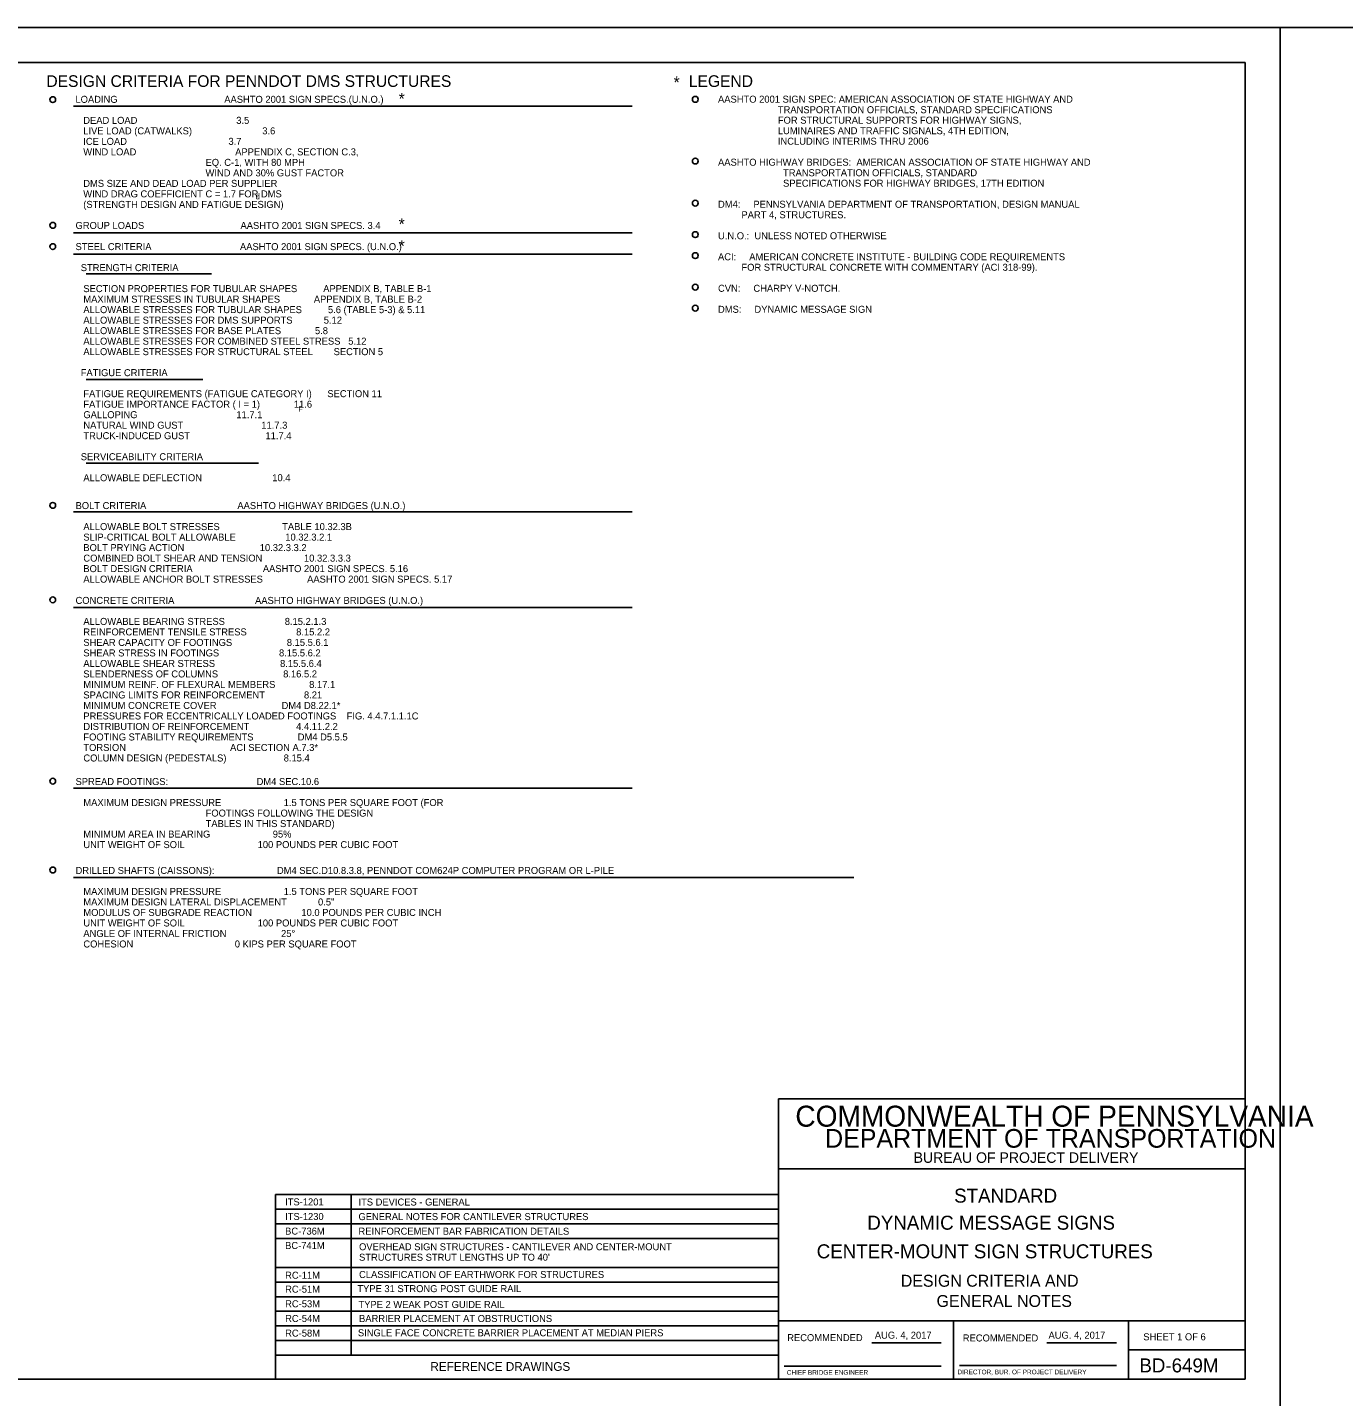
# Model space of a CAD drawing. Extents: x 3829340 to 3831660, y 499389 to 501171.
# Drawn here: x 3829644 to 3830208, y 500585 to 501171 of the extents above; entities that cross this region are included whole.
import ezdxf

# ---------------------------------------------------------------- set-up
doc = ezdxf.new("R2010")
doc.units = 0
for name, color, linetype in [('10', 7, 'Continuous'), ('13', 7, 'Continuous'), ('2', 7, 'Continuous'), ('DIM TXT', 7, 'Continuous'), ('PLT-BNDY', 7, 'Continuous')]:
    doc.layers.add(name, color=color, linetype=linetype)

msp = doc.modelspace()

# ---------------------------------------------------------------- linework, layer by layer
at = {"layer": '10'}
for p, q in [((3829664.03, 501137.44), (3829903.36, 501137.44)), ((3829664.03, 501083.16), (3829903.36, 501083.16)), ((3829664.03, 501073.99), (3829903.36, 501073.99)), ((3829669.36, 501065.68), (3829723.15, 501065.68)), ((3829669.36, 501020.29), (3829719.35, 501020.29)), ((3829669.36, 500984.49), (3829743.23, 500984.49)), ((3829664.03, 500963.68), (3829903.36, 500963.68)), ((3829664.03, 500922.74), (3829903.36, 500922.74)), ((3829664.03, 500845.32), (3829903.36, 500845.32)), ((3829664.03, 500807.06), (3829998.27, 500807.06))]:
    msp.add_line(p, q, dxfattribs=at)
at = {"layer": '13'}
for p, q in [((3829750.49, 500671.23), (3829965.96, 500671.23)), ((3829750.5, 500592.19), (3829750.5, 500671.23)), ((3829782.96, 500602.47), (3829782.96, 500671.23)), ((3829750.49, 500664.98), (3829965.96, 500664.98)), ((3829750.49, 500658.73), (3829965.96, 500658.73)), ((3829750.49, 500652.48), (3829965.96, 500652.48)), ((3829750.49, 500639.98), (3829965.96, 500639.98)), ((3829750.49, 500633.73), (3829965.96, 500633.73)), ((3829750.49, 500627.48), (3829965.96, 500627.48)), ((3829750.49, 500621.23), (3829965.96, 500621.23)), ((3829750.49, 500614.98), (3829965.96, 500614.98)), ((3829750.49, 500608.72), (3829965.96, 500608.72)), ((3829750.49, 500602.47), (3829965.96, 500602.47))]:
    msp.add_line(p, q, dxfattribs=at)
at = {"layer": '2'}
for p, q in [((3829379.96, 501156.19), (3830165.96, 501156.19)), ((3830165.96, 501156.19), (3830165.96, 500592.19)), ((3830165.96, 500712.19), (3829965.96, 500712.19)), ((3829965.96, 500712.19), (3829965.96, 500592.19)), ((3830165.96, 500682.19), (3829965.96, 500682.19)), ((3830165.96, 500617.19), (3829965.96, 500617.19)), ((3830040.96, 500592.19), (3830040.96, 500617.19)), ((3830115.96, 500617.19), (3830115.96, 500592.19)), ((3830005.93, 500607.69), (3830035.69, 500607.69)), ((3830080.93, 500607.69), (3830110.83, 500607.69)), ((3830115.96, 500604.69), (3830165.96, 500604.69)), ((3829968.46, 500597.69), (3830035.69, 500597.69)), ((3830043.59, 500598.06), (3830110.83, 500598.06)), ((3830165.96, 500592.19), (3829379.96, 500592.19)), ((3829965.96, 500592.19), (3829968.53, 500592.19))]:
    msp.add_line(p, q, dxfattribs=at)
at = {"layer": 'DIM TXT'}
for centre in [(3829655.1, 501140.24), (3829655.1, 501140.24), (3829930.36, 501140.37), (3829930.36, 501113.92), (3829930.36, 501095.92), (3829655.1, 501086.4), (3829930.36, 501082.42), (3829655.1, 501077.29), (3829930.36, 501073.43), (3829930.36, 501059.93), (3829930.36, 501050.93), (3829655.1, 500966.44), (3829655.1, 500925.96), (3829655.1, 500848.32), (3829655.1, 500810.26)]:
    msp.add_circle(centre, 1.25, dxfattribs=at)
at = {"layer": 'PLT-BNDY'}
for points in [[(3829339.96, 501171.19), (3830180.96, 501171.19), (3830180.96, 500577.19), (3829339.96, 500577.19)], [(3830180.96, 501171.19), (3831021.96, 501171.19), (3831021.96, 500577.19), (3830180.96, 500577.19)]]:
    msp.add_lwpolyline(points, close=True, dxfattribs=at)

# ---------------------------------------------------------------- texts
at = {"layer": '10'}
for s, height, p in [('STANDARD ', 6, (3830041.23, 500667.77)), ('ITS-1201', 3, (3829754.65, 500666.59)), ('ITS DEVICES - GENERAL', 3.0001, (3829786.07, 500666.54)), ('ITS-1230', 3, (3829754.65, 500660.34)), ('GENERAL NOTES FOR CANTILEVER STRUCTURES', 3.0001, (3829786.07, 500660.29)), ('DYNAMIC MESSAGE SIGNS', 6, (3830004.03, 500656.18)), ('BC-736M', 3, (3829754.65, 500654.08)), ('REINFORCEMENT BAR FABRICATION DETAILS', 3.0001, (3829786.07, 500654.04)), ('BC-741M', 3, (3829754.65, 500647.92)), ('OVERHEAD SIGN STRUCTURES - CANTILEVER AND CENTER-MOUNT', 3.0001, (3829786.32, 500647.38)), ('CENTER-MOUNT SIGN STRUCTURES', 6, (3829982.36, 500643.92)), ("STRUCTURES STRUT LENGTHS UP TO 40'", 3.0001, (3829786.32, 500642.88)), ('RC-11M', 3, (3829754.65, 500635.18)), ('CLASSIFICATION OF EARTHWORK FOR STRUCTURES', 3.0001, (3829786.32, 500635.5)), ('DESIGN CRITERIA AND', 5.1, (3830018.39, 500631.76)), ('RC-51M', 3, (3829754.65, 500629.21)), ('TYPE 31 STRONG POST GUIDE RAIL', 3.0001, (3829785.58, 500629.44)), ('RC-53M', 3, (3829754.65, 500622.94)), ('TYPE 2 WEAK POST GUIDE RAIL', 3.0001, (3829786.07, 500622.65)), ('GENERAL NOTES', 5.1, (3830033.71, 500623.09)), ('RC-54M', 3, (3829754.65, 500616.66)), ('BARRIER PLACEMENT AT OBSTRUCTIONS', 3.0001, (3829786.32, 500616.64)), ('RC-58M', 3, (3829754.65, 500610.39)), ('SINGLE FACE CONCRETE BARRIER PLACEMENT AT MEDIAN PIERS', 3.0001, (3829785.83, 500610.53)), ('REFERENCE DRAWINGS', 3.7501, (3829816.87, 500595.72))]:
    msp.add_text(s, height=height, dxfattribs=at).set_placement(p)
at = {"layer": '2'}
for s, height, p in [('COMMONWEALTH OF PENNSYLVANIA', 9, (3829973.21, 500700.31)), ('DEPARTMENT OF TRANSPORTATION', 8.0002, (3829985.96, 500691.31)), ('BUREAU OF PROJECT DELIVERY', 4.5, (3830023.88, 500684.82)), ('RECOMMENDED', 3, (3829969.73, 500608.44)), ('RECOMMENDED', 3, (3830044.95, 500608.31))]:
    msp.add_text(s, height=height, rotation=360, dxfattribs=at).set_placement(p)
for s, height, p in [('AUG. 4, 2017', 3, (3830007.27, 500609.5)), ('AUG. 4, 2017', 3, (3830081.66, 500609.5)), ('SHEET 1 OF 6', 3, (3830122.27, 500608.81)), ('CHIEF BRIDGE ENGINEER', 2.0002, (3829969.55, 500594.06)), ('  DIRECTOR, BUR. OF PROJECT DELIVERY', 2.0002, (3830041.15, 500594.24)), ('BD-649M', 6, (3830120.59, 500595.06))]:
    msp.add_text(s, height=height, dxfattribs=at).set_placement(p)
at = {"layer": 'DIM TXT'}
for s, height, p in [('DESIGN CRITERIA FOR PENNDOT DMS STRUCTURES', 4.9999, (3829652.37, 501145.68)), ('*', 5, (3829921.07, 501145.16)), ('LEGEND', 5, (3829927.59, 501145.67)), ('LOADING                                         AASHTO 2001 SIGN SPECS.(U.N.O.)', 2.9999, (3829664.83, 501138.87)), ('*', 5, (3829803.29, 501138.13)), ('AASHTO 2001 SIGN SPEC: AMERICAN ASSOCIATION OF STATE HIGHWAY AND', 2.9999, (3829940.09, 501138.93)), ('                       TRANSPORTATION OFFICIALS, STANDARD SPECIFICATIONS', 2.9999, (3829940.09, 501134.43)), ('   DEAD LOAD                                      3.5 ', 2.9999, (3829664.83, 501129.87)), ('                       FOR STRUCTURAL SUPPORTS FOR HIGHWAY SIGNS,', 2.9999, (3829940.09, 501129.93)), ('   LIVE LOAD (CATWALKS)                           3.6', 2.9999, (3829664.83, 501125.37)), ('   ICE LOAD                                       3.7', 2.9999, (3829664.83, 501120.87)), ('                       LUMINAIRES AND TRAFFIC SIGNALS, 4TH EDITION,', 2.9999, (3829940.09, 501125.43)), ('                       INCLUDING INTERIMS THRU 2006', 2.9999, (3829940.09, 501120.93)), ('   WIND LOAD                                      APPENDIX C, SECTION C.3, ', 2.9999, (3829664.83, 501116.37)), ('                                                  EQ. C-1, WITH 80 MPH ', 2.9999, (3829664.83, 501111.87)), ('AASHTO HIGHWAY BRIDGES:  AMERICAN ASSOCIATION OF STATE HIGHWAY AND', 2.9999, (3829940.09, 501111.93)), ('   DMS SIZE AND DEAD LOAD PER SUPPLIER', 2.9999, (3829664.83, 501102.87)), ('                                                  WIND AND 30% GUST FACTOR', 2.9999, (3829664.83, 501107.37)), ('                         TRANSPORTATION OFFICIALS, STANDARD', 2.9999, (3829940.09, 501107.43)), ('                         SPECIFICATIONS FOR HIGHWAY BRIDGES, 17TH EDITION', 2.9999, (3829940.09, 501102.93)), ('   WIND DRAG COEFFICIENT C = 1.7 FOR DMS', 2.9999, (3829664.83, 501098.37)), ('d', 2.5, (3829742.02, 501097.55)), ('   (STRENGTH DESIGN AND FATIGUE DESIGN)', 2.9999, (3829664.83, 501093.87)), ('DM4:     PENNSYLVANIA DEPARTMENT OF TRANSPORTATION, DESIGN MANUAL', 2.9999, (3829940.09, 501093.93)), ('*', 5, (3829803.29, 501084.43)), ('         PART 4, STRUCTURES.', 2.9999, (3829940.09, 501089.43)), ('GROUP LOADS                                     AASHTO 2001 SIGN SPECS. 3.4', 2.9999, (3829664.87, 501084.85)), ('U.N.O.:  UNLESS NOTED OTHERWISE', 2.9999, (3829940.09, 501080.43)), ('STEEL CRITERIA                                  AASHTO 2001 SIGN SPECS. (U.N.O.)', 2.9999, (3829664.87, 501075.78)), ('*', 5, (3829803.29, 501075.04)), ('ACI:     AMERICAN CONCRETE INSTITUTE - BUILDING CODE REQUIREMENTS', 2.9999, (3829940.09, 501071.43)), ('  STRENGTH CRITERIA', 2.9999, (3829664.87, 501066.78)), ('         FOR STRUCTURAL CONCRETE WITH COMMENTARY (ACI 318-99).', 2.9999, (3829940.09, 501066.93)), ('   SECTION PROPERTIES FOR TUBULAR SHAPES          APPENDIX B, TABLE B-1', 2.9999, (3829664.87, 501057.78)), ('CVN:     CHARPY V-NOTCH.', 2.9999, (3829940.09, 501057.93)), ('   MAXIMUM STRESSES IN TUBULAR SHAPES             APPENDIX B, TABLE B-2', 2.9999, (3829664.87, 501053.28)), ('   ALLOWABLE STRESSES FOR TUBULAR SHAPES          5.6 (TABLE 5-3) & 5.11', 2.9999, (3829664.87, 501048.78)), ('   ALLOWABLE STRESSES FOR DMS SUPPORTS            5.12', 2.9999, (3829664.87, 501044.28)), ('DMS:     DYNAMIC MESSAGE SIGN', 2.9999, (3829940.09, 501048.93)), ('   ALLOWABLE STRESSES FOR BASE PLATES             5.8', 2.9999, (3829664.87, 501039.78)), ('   ALLOWABLE STRESSES FOR COMBINED STEEL STRESS   5.12', 2.9999, (3829664.87, 501035.28)), ('   ALLOWABLE STRESSES FOR STRUCTURAL STEEL        SECTION 5', 2.9999, (3829664.87, 501030.79)), ('  FATIGUE CRITERIA', 2.9999, (3829664.87, 501021.79)), ('   FATIGUE REQUIREMENTS (FATIGUE CATEGORY I)      SECTION 11', 2.9999, (3829664.87, 501012.79)), ('   GALLOPING                                      11.7.1', 2.9999, (3829664.87, 501003.79)), ('   FATIGUE IMPORTANCE FACTOR ( I = 1)             11.6', 2.9999, (3829664.87, 501008.29)), ('F', 2.25, (3829760.3, 501006.61)), ('   NATURAL WIND GUST                              11.7.3', 2.9999, (3829664.87, 500999.29)), ('   TRUCK-INDUCED GUST                             11.7.4', 2.9999, (3829664.87, 500994.79)), ('  SERVICEABILITY CRITERIA', 2.9999, (3829664.87, 500985.79)), ('   ALLOWABLE DEFLECTION                           10.4', 2.9999, (3829664.87, 500976.79)), ('BOLT CRITERIA                                   AASHTO HIGHWAY BRIDGES (U.N.O.)', 2.9999, (3829664.87, 500964.85)), ('   ALLOWABLE BOLT STRESSES                        TABLE 10.32.3B', 2.9999, (3829664.87, 500955.85)), ('   SLIP-CRITICAL BOLT ALLOWABLE                   10.32.3.2.1', 2.9999, (3829664.87, 500951.35)), ('   BOLT PRYING ACTION                             10.32.3.3.2', 2.9999, (3829664.87, 500946.85)), ('   COMBINED BOLT SHEAR AND TENSION                10.32.3.3.3', 2.9999, (3829664.87, 500942.35)), ('   ALLOWABLE ANCHOR BOLT STRESSES                 AASHTO 2001 SIGN SPECS. 5.17', 2.9999, (3829664.87, 500933.35)), ('   BOLT DESIGN CRITERIA                           AASHTO 2001 SIGN SPECS. 5.16', 2.9999, (3829664.87, 500937.85)), ('CONCRETE CRITERIA                               AASHTO HIGHWAY BRIDGES (U.N.O.)', 2.9999, (3829664.87, 500924.24)), ('   ALLOWABLE BEARING STRESS                       8.15.2.1.3', 2.9999, (3829664.87, 500915.24)), ('   REINFORCEMENT TENSILE STRESS                   8.15.2.2', 2.9999, (3829664.87, 500910.74)), ('   SHEAR CAPACITY OF FOOTINGS                     8.15.5.6.1', 2.9999, (3829664.87, 500906.24)), ('   SHEAR STRESS IN FOOTINGS                       8.15.5.6.2', 2.9999, (3829664.87, 500901.74)), ('   ALLOWABLE SHEAR STRESS                         8.15.5.6.4', 2.9999, (3829664.87, 500897.24)), ('   SLENDERNESS OF COLUMNS                         8.16.5.2', 2.9999, (3829664.87, 500892.74)), ('   MINIMUM REINF. OF FLEXURAL MEMBERS             8.17.1', 2.9999, (3829664.87, 500888.24)), ('   SPACING LIMITS FOR REINFORCEMENT               8.21', 2.9999, (3829664.87, 500883.74)), ('   MINIMUM CONCRETE COVER                         DM4 D8.22.1*', 2.9999, (3829664.87, 500879.24)), ('   PRESSURES FOR ECCENTRICALLY LOADED FOOTINGS    FIG. 4.4.7.1.1.1C', 2.9999, (3829664.87, 500874.74)), ('   DISTRIBUTION OF REINFORCEMENT                  4.4.11.2.2', 2.9999, (3829664.87, 500870.24)), ('   FOOTING STABILITY REQUIREMENTS                 DM4 D5.5.5', 2.9999, (3829664.87, 500865.74)), ('   TORSION                                        ACI SECTION A.7.3*', 2.9999, (3829664.87, 500861.24)), ('   COLUMN DESIGN (PEDESTALS)                      8.15.4', 2.9999, (3829664.87, 500856.74)), ('SPREAD FOOTINGS:                                  DM4 SEC.10.6', 2.9999, (3829664.87, 500846.64)), ('   MAXIMUM DESIGN PRESSURE                        1.5 TONS PER SQUARE FOOT (FOR', 2.9999, (3829664.87, 500837.64)), ('                                                  FOOTINGS FOLLOWING THE DESIGN', 2.9999, (3829664.87, 500833.14)), ('                                                  TABLES IN THIS STANDARD)', 2.9999, (3829664.87, 500828.64)), ('   MINIMUM AREA IN BEARING                        95%', 2.9999, (3829664.87, 500824.14)), ('   UNIT WEIGHT OF SOIL                            100 POUNDS PER CUBIC FOOT', 2.9999, (3829664.87, 500819.64)), ('DRILLED SHAFTS (CAISSONS):                        DM4 SEC.D10.8.3.8, PENNDOT COM624P COMPUTER PROGRAM OR L-PILE', 2.99992, (3829664.87, 500808.57)), ('   MAXIMUM DESIGN PRESSURE                        1.5 TONS PER SQUARE FOOT', 2.9999, (3829664.87, 500799.57)), ('   MAXIMUM DESIGN LATERAL DISPLACEMENT            0.5"', 2.9999, (3829664.87, 500795.07)), ('   UNIT WEIGHT OF SOIL                            100 POUNDS PER CUBIC FOOT', 2.9999, (3829664.87, 500786.07)), ('   MODULUS OF SUBGRADE REACTION                   10.0 POUNDS PER CUBIC INCH', 2.9999, (3829664.87, 500790.57)), ('   ANGLE OF INTERNAL FRICTION                     25%%d  ', 2.9999, (3829664.87, 500781.57)), ('   COHESION                                       0 KIPS PER SQUARE FOOT', 2.9999, (3829664.87, 500777.07))]:
    msp.add_text(s, height=height, dxfattribs=at).set_placement(p)

doc.saveas('drawing.dxf')
